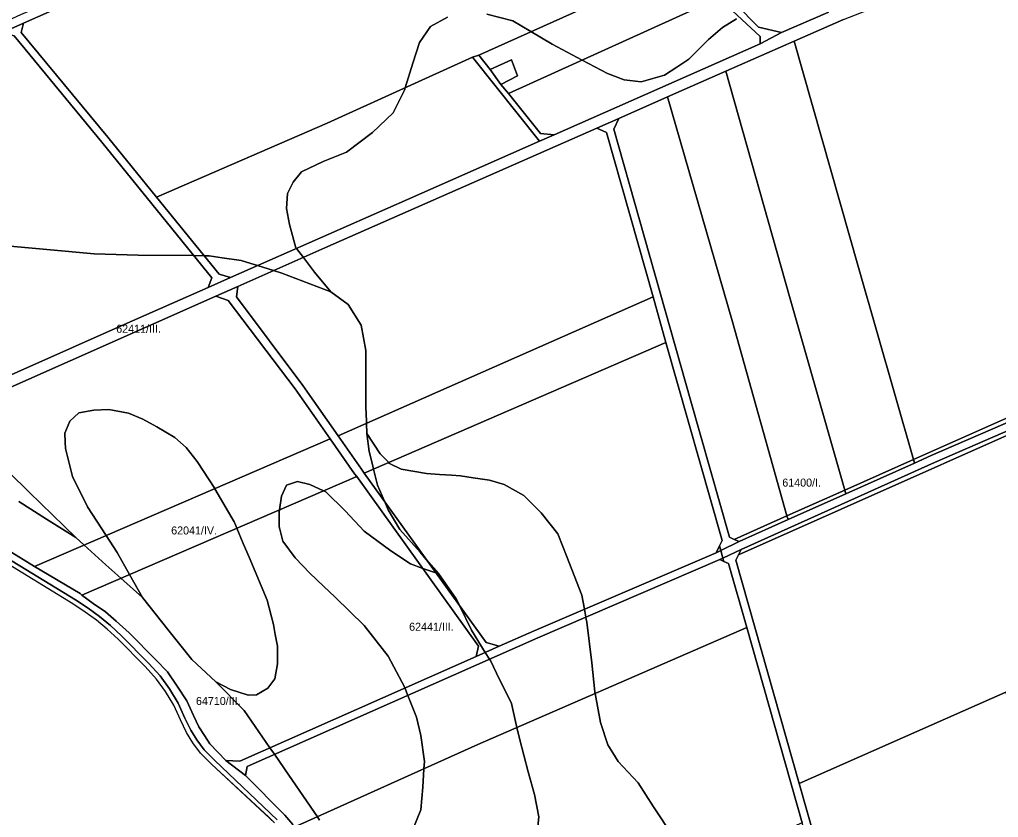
# Model space of a CAD drawing. Extents: x -522079 to -518833, y -1142400 to -1139961.
# Drawn here: x -521597 to -520985, y -1141508 to -1141010 of the extents above; entities that cross this region are included whole.
import ezdxf

# ---------------------------------------------------------------- set-up
doc = ezdxf.new("R2010")
doc.units = 0
for name, color, linetype in [('95560013', 7, 'Continuous'), ('95620013', 7, 'Continuous'), ('95630013', 7, 'Continuous'), ('95640013', 7, 'Continuous'), ('95660013', 7, 'Continuous')]:
    doc.layers.add(name, color=color, linetype=linetype)

msp = doc.modelspace()

# ---------------------------------------------------------------- linework, layer by layer
at = {"layer": '95560013'}
for points in [[(-521288.46, -1140863.02), (-521283.24, -1140866.3), (-521272.67, -1140872.95), (-521285.04, -1140873.12), (-521453.3, -1140949.4), (-521594.31, -1141011.83), (-521607.81, -1141017.81), (-521735.67, -1141074.42), (-521844.44, -1141121.41), (-521845.59, -1141127.96), (-521855.85, -1141115.33), (-521847.83, -1141117.27), (-521813.35, -1141102.46), (-521737.51, -1141069.87), (-521612.22, -1141013.76), (-521597.65, -1141007.23), (-521455.15, -1140944.86), (-521289.17, -1140869.28)], [(-521453.3, -1140949.4), (-521285.04, -1140873.12), (-521272.67, -1140872.95), (-521180.73, -1140973.62), (-521309.93, -1141031.69), (-521313.87, -1141033.11), (-521404.59, -1141074.2), (-521511.15, -1141120.5), (-521541.57, -1141083.01), (-521595.68, -1141017.57), (-521594.31, -1141011.83)], [(-520895.4, -1141219.71), (-520895.96, -1141221.04), (-521038.45, -1141284.46), (-521072.62, -1141164.33), (-521112.83, -1141022.98), (-521082.18, -1141009.47), (-521026.59, -1140987.63), (-520970.5, -1140967.09), (-520964.29, -1140970.32), (-520927.66, -1141102.94)], [(-521296.08, -1141050.04), (-521285.67, -1141044.64), (-521289.36, -1141034.73), (-521302.83, -1141040.76), (-521309.93, -1141031.69), (-521180.73, -1140973.62), (-521160.03, -1140995.91), (-521291.39, -1141055.81)], [(-521134.18, -1141024.63), (-521223.67, -1141064.26), (-521262.72, -1141081.47), (-521271.3, -1141080.74), (-521291.39, -1141055.81), (-521160.03, -1140995.91), (-521134.23, -1141020.21)], [(-521464.85, -1141170.68), (-521478.81, -1141176.87), (-521476.67, -1141170.91), (-521545.26, -1141086.06), (-521600.08, -1141019.71), (-521607.81, -1141017.81), (-521594.31, -1141011.83), (-521595.68, -1141017.57), (-521541.57, -1141083.01), (-521511.15, -1141120.5), (-521472.07, -1141168.66)], [(-521705, -1141272.16), (-521746.52, -1141232.38), (-521780.54, -1141201.02), (-521789.46, -1141193.57), (-521801.69, -1141180.84), (-521813.1, -1141167.95), (-521845.59, -1141127.96), (-521844.44, -1141121.41), (-521735.67, -1141074.42), (-521607.81, -1141017.81), (-521600.08, -1141019.71), (-521545.26, -1141086.06), (-521476.67, -1141170.91), (-521478.81, -1141176.87), (-521531.28, -1141200.09), (-521696.71, -1141273.51)], [(-521112.83, -1141022.98), (-521072.62, -1141164.33), (-521038.45, -1141284.46), (-521081.35, -1141303.56), (-521115.71, -1141182.49), (-521155.63, -1141041.85)], [(-521354.37, -1141121.84), (-521464.85, -1141170.68), (-521472.07, -1141168.66), (-521511.15, -1141120.5), (-521404.59, -1141074.2), (-521313.87, -1141033.11), (-521271.86, -1141085.49)], [(-521313.87, -1141033.11), (-521309.93, -1141031.69), (-521302.83, -1141040.76), (-521296.08, -1141050.04), (-521291.39, -1141055.81), (-521271.3, -1141080.74), (-521262.72, -1141081.47), (-521271.86, -1141085.49)], [(-521155.63, -1141041.85), (-521115.71, -1141182.49), (-521081.35, -1141303.56), (-521117.38, -1141319.6), (-521151.45, -1141198.34), (-521191.96, -1141057.88)], [(-521177.35, -1141247.92), (-521225.53, -1141078.04), (-521222.3, -1141071.25), (-521191.96, -1141057.88), (-521151.45, -1141198.34), (-521117.38, -1141319.6), (-521150.33, -1141334.27), (-521153.24, -1141332.9)], [(-521419.75, -1141238.15), (-521461.21, -1141182.74), (-521460.33, -1141176.23), (-521405.94, -1141152.24), (-521236.08, -1141077.32), (-521230.09, -1141080.11), (-521201.01, -1141182.77), (-521328.3, -1141238.94), (-521397.78, -1141269.61)], [(-521474.13, -1141182.35), (-521460.33, -1141176.23), (-521461.21, -1141182.74), (-521419.75, -1141238.15), (-521397.78, -1141269.61), (-521383.22, -1141290.47), (-521381.4, -1141292.99), (-521305.3, -1141398.78), (-521297.15, -1141401.04), (-521311.57, -1141407.43), (-521310.04, -1141400.96), (-521386.12, -1141295.04), (-521387.39, -1141293.27), (-521402.72, -1141271.39), (-521424.55, -1141240.21), (-521466.3, -1141184.96)], [(-521587.36, -1141351.16), (-521604.24, -1141340.75), (-521628.15, -1141324.02), (-521671.77, -1141299.69), (-521692.02, -1141284.07), (-521691.15, -1141278.7), (-521609.81, -1141242.59), (-521474.13, -1141182.35), (-521466.3, -1141184.96), (-521424.55, -1141240.21), (-521402.72, -1141271.39)], [(-521192.96, -1141211.21), (-521381.4, -1141292.99), (-521383.22, -1141290.47), (-521397.78, -1141269.61), (-521328.3, -1141238.94), (-521201.01, -1141182.77)], [(-521157.91, -1141334.94), (-521159.51, -1141338.32), (-521161.56, -1141342.65), (-521275.3, -1141391.36), (-521297.15, -1141401.04), (-521305.3, -1141398.78), (-521381.4, -1141292.99), (-521192.96, -1141211.21)], [(-520851.22, -1141372.34), (-520980.65, -1141429.68), (-521109.72, -1141486.85), (-521149.23, -1141347.36), (-521147.68, -1141344.03), (-520893.13, -1141230.74), (-520889.86, -1141232.13)], [(-521387.39, -1141293.27), (-521386.12, -1141295.04), (-521557.71, -1141369.1), (-521558.92, -1141368.2), (-521587.36, -1141351.16), (-521402.72, -1141271.39)], [(-521386.12, -1141295.04), (-521310.04, -1141400.96), (-521311.57, -1141407.43), (-521459, -1141472.78), (-521467.85, -1141472.41), (-521477.75, -1141461.99), (-521481.18, -1141456.84), (-521484.69, -1141451.44), (-521488.03, -1141444.36), (-521492.17, -1141435.06), (-521498.23, -1141425.96), (-521504.19, -1141417.07), (-521511.47, -1141409.59), (-521528.31, -1141392.77), (-521536.29, -1141385.49), (-521543.06, -1141379.52), (-521550.74, -1141374.27), (-521557.71, -1141369.1)], [(-521161.56, -1141342.65), (-521159.51, -1141338.32), (-521158.68, -1141341.24)], [(-521467.85, -1141472.41), (-521459, -1141472.78), (-521311.57, -1141407.43), (-521297.15, -1141401.04), (-521275.3, -1141391.36), (-521161.56, -1141342.65), (-521158.68, -1141341.24), (-521157.35, -1141345.97), (-521159.26, -1141346.88), (-521272.96, -1141395.84), (-521454.54, -1141476.12), (-521455.62, -1141481.81)], [(-521431.09, -1141506.63), (-521455.62, -1141481.81), (-521454.54, -1141476.12), (-521272.96, -1141395.84), (-521159.26, -1141346.88), (-521156.76, -1141348.04), (-521153.82, -1141349.39), (-521142.48, -1141389.44), (-521310.56, -1141462.49), (-521425.07, -1141514.17), (-521426.04, -1141512.48)], [(-521156.76, -1141348.04), (-521159.26, -1141346.88), (-521157.35, -1141345.97)], [(-521378.39, -1141629.5), (-521389.3, -1141621.72), (-521393.54, -1141617.98), (-521399.61, -1141612.42), (-521404.05, -1141606.86), (-521406.05, -1141602.85), (-521409.49, -1141593.05), (-521412.01, -1141585.06), (-521414.13, -1141574.69), (-521415.34, -1141566.3), (-521417.47, -1141538.2), (-521418.07, -1141529.55), (-521421, -1141521.26), (-521425.07, -1141514.17), (-521310.56, -1141462.49), (-521142.48, -1141389.44), (-521107.96, -1141511.35), (-521234.07, -1141566.44)], [(-520980.65, -1141429.68), (-520955.18, -1141519.6), (-521084.21, -1141576.91), (-521109.72, -1141486.85)]]:
    msp.add_lwpolyline(points, close=True, dxfattribs=at)
at = {"layer": '95620013'}
msp.add_lwpolyline([(-521283.37, -1140860.94), (-521307.86, -1140833.61), (-521298.55, -1140826.47), (-521220.23, -1140832.37), (-521184.18, -1140870.5), (-521185.72, -1140871.68), (-521143.12, -1140927.46), (-521088.9, -1141000.66), (-521091.97, -1141005.03), (-521120.79, -1141017.67), (-521135.25, -1141014.2), (-521191.17, -1140957.11), (-521275.9, -1140861.47), (-521279.53, -1140861.89)], close=True, dxfattribs=at)
at = {"layer": '95630013'}
for points in [[(-521437.41, -1141511.31), (-521476.9, -1141474.65), (-521483.59, -1141467.79), (-521488.42, -1141461.33), (-521492.43, -1141454.93), (-521496.24, -1141447.12), (-521500.39, -1141437.89), (-521505.54, -1141429.29), (-521511.22, -1141421.52), (-521518.22, -1141413.8), (-521535.13, -1141396.73), (-521541.97, -1141390.39), (-521548.66, -1141384.81), (-521555.61, -1141379.71), (-521563.41, -1141374.64), (-521610.54, -1141345.88)], [(-521608.95, -1141343.32), (-521561.83, -1141372.1), (-521553.85, -1141377.26), (-521546.79, -1141382.47), (-521539.97, -1141388.19), (-521532.97, -1141394.62), (-521516.02, -1141411.74), (-521508.94, -1141419.63), (-521503.06, -1141427.66), (-521497.72, -1141436.55), (-521493.43, -1141445.97), (-521489.81, -1141453.49), (-521485.96, -1141459.56), (-521481.44, -1141465.72), (-521474.82, -1141472.48), (-521435.7, -1141509.5)]]:
    msp.add_lwpolyline(points, dxfattribs=at)
at = {"layer": '95640013'}
for points in [[(-521134.18, -1141024.63), (-521134.23, -1141020.21), (-521160.03, -1140995.91), (-521180.73, -1140973.62), (-521272.67, -1140872.95), (-521283.24, -1140866.3), (-521275.9, -1140861.47), (-521191.17, -1140957.11), (-521135.25, -1141014.2), (-521120.79, -1141017.67)], [(-521285.67, -1141044.64), (-521296.08, -1141050.04), (-521302.83, -1141040.76), (-521289.36, -1141034.73)], [(-521222.3, -1141071.25), (-521225.53, -1141078.04), (-521177.35, -1141247.92), (-521153.24, -1141332.9), (-521150.33, -1141334.27), (-521147.33, -1141335.67), (-521158.68, -1141341.24), (-521159.51, -1141338.32), (-521157.91, -1141334.94), (-521192.96, -1141211.21), (-521201.01, -1141182.77), (-521230.09, -1141080.11), (-521236.08, -1141077.32)], [(-520895.96, -1141221.04), (-520897.83, -1141225.78), (-521027.41, -1141281.92), (-521037.84, -1141286.59), (-521038.45, -1141284.46)], [(-520893.13, -1141230.74), (-521147.68, -1141344.03), (-521146.08, -1141340.6), (-521025.25, -1141286.2), (-520895.38, -1141229.74)], [(-521037.84, -1141286.59), (-521080.71, -1141305.81), (-521081.35, -1141303.56), (-521038.45, -1141284.46)], [(-521081.35, -1141303.56), (-521080.71, -1141305.81), (-521116.71, -1141321.95), (-521117.38, -1141319.6)], [(-521147.33, -1141335.67), (-521150.33, -1141334.27), (-521117.38, -1141319.6), (-521116.71, -1141321.95)], [(-521147.68, -1141344.03), (-521149.23, -1141347.36), (-521109.72, -1141486.85), (-521084.21, -1141576.91), (-521078.78, -1141596.05), (-521077.42, -1141600.82), (-521086.66, -1141604.9), (-521083.41, -1141598.05), (-521107.96, -1141511.35), (-521142.48, -1141389.44), (-521153.82, -1141349.39), (-521156.76, -1141348.04), (-521157.35, -1141345.97), (-521146.08, -1141340.6)]]:
    msp.add_lwpolyline(points, close=True, dxfattribs=at)
for points in [[(-521082.18, -1141009.47), (-521112.83, -1141022.98), (-521155.63, -1141041.85), (-521191.96, -1141057.88), (-521222.3, -1141071.25), (-521236.08, -1141077.32), (-521405.94, -1141152.24), (-521460.33, -1141176.23), (-521474.13, -1141182.35), (-521609.81, -1141242.59), (-521691.15, -1141278.7), (-521692.02, -1141284.07), (-521705, -1141272.16), (-521696.71, -1141273.51), (-521531.28, -1141200.09), (-521478.81, -1141176.87), (-521464.85, -1141170.68), (-521354.37, -1141121.84), (-521271.86, -1141085.49), (-521262.72, -1141081.47), (-521223.67, -1141064.26), (-521134.18, -1141024.63), (-521120.79, -1141017.67), (-521091.97, -1141005.03)], [(-520895.38, -1141229.74), (-521025.25, -1141286.2), (-521146.08, -1141340.6), (-521157.35, -1141345.97), (-521158.68, -1141341.24), (-521147.33, -1141335.67), (-521116.71, -1141321.95), (-521080.71, -1141305.81), (-521037.84, -1141286.59), (-521027.41, -1141281.92), (-520897.83, -1141225.78)], [(-521604.24, -1141340.75), (-521587.36, -1141351.16), (-521558.92, -1141368.2), (-521557.71, -1141369.1), (-521550.74, -1141374.27), (-521543.06, -1141379.52), (-521536.29, -1141385.49), (-521528.31, -1141392.77), (-521511.47, -1141409.59), (-521504.19, -1141417.07), (-521498.23, -1141425.96), (-521492.17, -1141435.06), (-521488.03, -1141444.36), (-521484.69, -1141451.44), (-521481.18, -1141456.84), (-521477.75, -1141461.99), (-521467.85, -1141472.41), (-521455.62, -1141481.81), (-521431.09, -1141506.63), (-521426.04, -1141512.48)], [(-521435.7, -1141509.5), (-521474.82, -1141472.48), (-521481.44, -1141465.72), (-521485.96, -1141459.56), (-521489.81, -1141453.49), (-521493.43, -1141445.97), (-521497.72, -1141436.55), (-521503.06, -1141427.66), (-521508.94, -1141419.63), (-521516.02, -1141411.74), (-521532.97, -1141394.62), (-521539.97, -1141388.19), (-521546.79, -1141382.47), (-521553.85, -1141377.26), (-521561.83, -1141372.1), (-521608.95, -1141343.32)]]:
    msp.add_lwpolyline(points, dxfattribs=at)
at = {"layer": '95660013'}
for points in [[(-521329.43, -1141007.98), (-521339.94, -1141013.83), (-521346.95, -1141023.8), (-521351.04, -1141036.69), (-521355.81, -1141052.1), (-521356.3, -1141053.68), (-521363.31, -1141067.75), (-521376.16, -1141080.05), (-521392.52, -1141092.36), (-521407.12, -1141098.22), (-521420.56, -1141104.67), (-521425.81, -1141111.11), (-521426.69, -1141112.87), (-521429.32, -1141118.14), (-521429.9, -1141127.52), (-521428.15, -1141137.48), (-521424.06, -1141152.13), (-521423.76, -1141152.52), (-521419.42, -1141158.18), (-521412.38, -1141167.36), (-521402.29, -1141179.6), (-521432.87, -1141168.01), (-521438.03, -1141166.39), (-521448.04, -1141163.25), (-521452.23, -1141161.94), (-521458.24, -1141160.06), (-521470.15, -1141158.29), (-521478.17, -1141157.1), (-521479.52, -1141157.09), (-521481.47, -1141157.07), (-521487.91, -1141157), (-521522.57, -1141156.65), (-521549.98, -1141155.96), (-521579.71, -1141153.25), (-521604.79, -1141150.97)], [(-521188.48, -1141519.97), (-521200.71, -1141501.34), (-521210.22, -1141486.34), (-521222.9, -1141473.16), (-521226.22, -1141467.7), (-521229.25, -1141462.71), (-521233.78, -1141448.62), (-521237.2, -1141430.6), (-521237.4, -1141429.53), (-521239.21, -1141411.36), (-521242.38, -1141385.91), (-521242.72, -1141384.12), (-521242.95, -1141382.92), (-521243.89, -1141377.91), (-521245.55, -1141369.09), (-521251.72, -1141353.18), (-521255.07, -1141344.56), (-521257.4, -1141338.72), (-521260.5, -1141330.92), (-521270.92, -1141317.75), (-521281.8, -1141306.84), (-521294.03, -1141300.02), (-521303.09, -1141297.29), (-521313.39, -1141295.74), (-521321.21, -1141294.57), (-521327.01, -1141294.2), (-521334.39, -1141293.72), (-521342.5, -1141293.2), (-521358.35, -1141290.48), (-521365.6, -1141286.84), (-521366.09, -1141286.35), (-521371.49, -1141280.93), (-521379.87, -1141268.21), (-521380.05, -1141261.78), (-521380.06, -1141261.15), (-521380.08, -1141260.38), (-521380.32, -1141251.62), (-521380.32, -1141230.49), (-521380.32, -1141216.18), (-521383.27, -1141200.5), (-521391.42, -1141187.55), (-521402.29, -1141179.6), (-521412.38, -1141167.36), (-521419.42, -1141158.18), (-521423.76, -1141152.52), (-521424.06, -1141152.13), (-521428.15, -1141137.48), (-521429.9, -1141127.52), (-521429.32, -1141118.14), (-521426.69, -1141112.87), (-521425.81, -1141111.11), (-521420.56, -1141104.67), (-521407.12, -1141098.22), (-521392.52, -1141092.36), (-521376.16, -1141080.05), (-521363.31, -1141067.75), (-521356.3, -1141053.68), (-521355.81, -1141052.1), (-521351.04, -1141036.69), (-521346.95, -1141023.8), (-521339.94, -1141013.83), (-521329.43, -1141007.98)], [(-521304.89, -1141006.22), (-521288.54, -1141010.32), (-521277.31, -1141017.02), (-521264, -1141024.97), (-521245.33, -1141034.81), (-521229.54, -1141043.13), (-521219.02, -1141047.24), (-521208.51, -1141048.41), (-521193.9, -1141044.31), (-521186.08, -1141039.18), (-521178.72, -1141034.34), (-521177.36, -1141032.99), (-521166.45, -1141022.04), (-521157.69, -1141014.42), (-521148.92, -1141009.15)], [(-521148.92, -1141009.15), (-521157.69, -1141014.42), (-521166.45, -1141022.04), (-521177.36, -1141032.99), (-521178.72, -1141034.34), (-521186.08, -1141039.18), (-521193.9, -1141044.31), (-521208.51, -1141048.41), (-521219.02, -1141047.24), (-521229.54, -1141043.13), (-521245.33, -1141034.81), (-521264, -1141024.97), (-521277.31, -1141017.02), (-521288.54, -1141010.32), (-521304.89, -1141006.22)], [(-521604.79, -1141150.97), (-521579.71, -1141153.25), (-521549.98, -1141155.96), (-521522.57, -1141156.65), (-521487.91, -1141157), (-521481.47, -1141157.07), (-521479.52, -1141157.09), (-521478.17, -1141157.1), (-521470.15, -1141158.29), (-521458.24, -1141160.06), (-521452.23, -1141161.94), (-521448.04, -1141163.25), (-521438.03, -1141166.39), (-521432.87, -1141168.01), (-521402.29, -1141179.6), (-521391.42, -1141187.55), (-521383.27, -1141200.5), (-521380.32, -1141216.18), (-521380.32, -1141230.49), (-521380.32, -1141251.62), (-521380.08, -1141260.38), (-521380.06, -1141261.15), (-521380.05, -1141261.78), (-521379.87, -1141268.21), (-521378.28, -1141279.34), (-521376.46, -1141286.74), (-521375.55, -1141290.45), (-521373.08, -1141300.48), (-521368.83, -1141310.46), (-521366.51, -1141315.93), (-521359.26, -1141328.2), (-521346.57, -1141342.28), (-521342.67, -1141346.82), (-521335.08, -1141355.66), (-521336.68, -1141355.16), (-521342.95, -1141353.19), (-521344.88, -1141352.45), (-521352.46, -1141349.55), (-521364.7, -1141341.37), (-521381.46, -1141329.1), (-521393.24, -1141316.38), (-521405.47, -1141304.57), (-521406.27, -1141304.2), (-521406.79, -1141303.96), (-521415.43, -1141300.02), (-521423.13, -1141298.2), (-521429.93, -1141300.48), (-521433.1, -1141307.29), (-521434.26, -1141315.82), (-521434.46, -1141317.29), (-521434.46, -1141326.38), (-521434.1, -1141327.81), (-521432.19, -1141335.47), (-521424.49, -1141345.92), (-521415.43, -1141355.46), (-521406.81, -1141363.62), (-521399.58, -1141370.46), (-521381.46, -1141388.18), (-521366.51, -1141407.27), (-521356.09, -1141426.81), (-521355.97, -1141427.11), (-521354.17, -1141431.74), (-521348.84, -1141445.44), (-521346.12, -1141456.8), (-521343.86, -1141473.16), (-521344.11, -1141477.63), (-521344.76, -1141489.07), (-521346.12, -1141503.16), (-521350.65, -1141514.51)], [(-521409.25, -1141509.65), (-521410.62, -1141507.65), (-521428.44, -1141481.62), (-521437.49, -1141468.58), (-521440.32, -1141464.5), (-521456.46, -1141441.25), (-521474, -1141423.33), (-521465, -1141428.01), (-521454, -1141431.68), (-521448.67, -1141431.35), (-521441.67, -1141427.34), (-521437.34, -1141421.32), (-521435.67, -1141411.96), (-521435.67, -1141400.93), (-521436.94, -1141393.68), (-521438.01, -1141387.56), (-521442.01, -1141372.18), (-521453.34, -1141345.44), (-521456.99, -1141336.81), (-521460.98, -1141327.35), (-521462.31, -1141324.22), (-521462.67, -1141323.37), (-521474.66, -1141302.65), (-521474.75, -1141302.51), (-521485.66, -1141285.6), (-521492.66, -1141276.91), (-521499.66, -1141270.55), (-521510.99, -1141263.87), (-521519.65, -1141259.19), (-521528.65, -1141255.51), (-521540.98, -1141253.17), (-521550.31, -1141253.51), (-521559.64, -1141255.18), (-521565.31, -1141260.52), (-521568.31, -1141267.88), (-521568.11, -1141273.46), (-521567.97, -1141277.58), (-521563.64, -1141294.96), (-521554.31, -1141314.01), (-521542.61, -1141331.83), (-521535.65, -1141342.43), (-521527.94, -1141356.25), (-521519.98, -1141370.51), (-521533.36, -1141358.59), (-521542.73, -1141350.24), (-521556.45, -1141337.8), (-521561.53, -1141333.19), (-521590.75, -1141304.79), (-521615.66, -1141280.48)], [(-521274.09, -1141523.6), (-521272.28, -1141507.7), (-521275, -1141493.61), (-521279.08, -1141479.52), (-521284.51, -1141458.62), (-521286.06, -1141451.84), (-521289.5, -1141436.81), (-521298.8, -1141417.81), (-521302.63, -1141410), (-521303.14, -1141409.18), (-521305.8, -1141404.87), (-521314.41, -1141390.91), (-521321.64, -1141376.07), (-521322.95, -1141373.36), (-521323.92, -1141371.37), (-521335.08, -1141355.66), (-521342.67, -1141346.82), (-521346.57, -1141342.28), (-521359.26, -1141328.2), (-521366.51, -1141315.93), (-521368.83, -1141310.46), (-521373.08, -1141300.48), (-521375.55, -1141290.45), (-521376.46, -1141286.74), (-521378.28, -1141279.34), (-521379.87, -1141268.21), (-521371.49, -1141280.93), (-521366.09, -1141286.35), (-521365.6, -1141286.84), (-521358.35, -1141290.48), (-521342.5, -1141293.2), (-521334.39, -1141293.72), (-521327.01, -1141294.2), (-521321.21, -1141294.57), (-521313.39, -1141295.74), (-521303.09, -1141297.29), (-521294.03, -1141300.02), (-521281.8, -1141306.84), (-521270.92, -1141317.75), (-521260.5, -1141330.92), (-521257.4, -1141338.72), (-521255.07, -1141344.56), (-521251.72, -1141353.18), (-521245.55, -1141369.09), (-521243.89, -1141377.91), (-521242.95, -1141382.92), (-521242.72, -1141384.12), (-521242.38, -1141385.91), (-521239.21, -1141411.36), (-521237.4, -1141429.53), (-521237.2, -1141430.6), (-521233.78, -1141448.62), (-521229.25, -1141462.71), (-521226.22, -1141467.7), (-521222.9, -1141473.16), (-521210.22, -1141486.34), (-521200.71, -1141501.34), (-521188.48, -1141519.97)], [(-521615.66, -1141280.48), (-521590.75, -1141304.79), (-521561.53, -1141333.19), (-521579.88, -1141321.61), (-521597.19, -1141310.6)], [(-521350.65, -1141514.51), (-521346.12, -1141503.16), (-521344.76, -1141489.07), (-521344.11, -1141477.63), (-521343.86, -1141473.16), (-521346.12, -1141456.8), (-521348.84, -1141445.44), (-521354.17, -1141431.74), (-521355.97, -1141427.11), (-521356.09, -1141426.81), (-521366.51, -1141407.27), (-521381.46, -1141388.18), (-521399.58, -1141370.46), (-521406.81, -1141363.62), (-521415.43, -1141355.46), (-521424.49, -1141345.92), (-521432.19, -1141335.47), (-521434.1, -1141327.81), (-521434.46, -1141326.38), (-521434.46, -1141317.29), (-521434.26, -1141315.82), (-521433.1, -1141307.29), (-521429.93, -1141300.48), (-521423.13, -1141298.2), (-521415.43, -1141300.02), (-521406.79, -1141303.96), (-521406.27, -1141304.2), (-521405.47, -1141304.57), (-521393.24, -1141316.38), (-521381.46, -1141329.1), (-521364.7, -1141341.37), (-521352.46, -1141349.55), (-521344.88, -1141352.45), (-521342.95, -1141353.19), (-521336.68, -1141355.16), (-521335.08, -1141355.66), (-521323.92, -1141371.37), (-521322.95, -1141373.36), (-521321.64, -1141376.07), (-521314.41, -1141390.91), (-521305.8, -1141404.87), (-521303.14, -1141409.18), (-521302.63, -1141410), (-521298.8, -1141417.81), (-521289.5, -1141436.81), (-521286.06, -1141451.84), (-521284.51, -1141458.62), (-521279.08, -1141479.52), (-521275, -1141493.61), (-521272.28, -1141507.7), (-521274.09, -1141523.6)], [(-521597.19, -1141310.6), (-521579.88, -1141321.61), (-521561.53, -1141333.19), (-521556.45, -1141337.8), (-521542.73, -1141350.24), (-521533.36, -1141358.59), (-521519.98, -1141370.51), (-521503.32, -1141391.57), (-521488.99, -1141409.29), (-521474, -1141423.33), (-521456.46, -1141441.25), (-521440.32, -1141464.5), (-521437.49, -1141468.58), (-521428.44, -1141481.62), (-521410.62, -1141507.65), (-521409.25, -1141509.65)], [(-521437.41, -1141511.31), (-521441.06, -1141507.92), (-521476.9, -1141474.65), (-521483.59, -1141467.79), (-521488.42, -1141461.33), (-521492.43, -1141454.93), (-521496.24, -1141447.12), (-521500.39, -1141437.89), (-521505.54, -1141429.29), (-521511.22, -1141421.52), (-521518.22, -1141413.8), (-521535.13, -1141396.73), (-521541.97, -1141390.39), (-521548.66, -1141384.81), (-521555.61, -1141379.71), (-521563.41, -1141374.64), (-521610.54, -1141345.88)]]:
    msp.add_lwpolyline(points, dxfattribs=at)
msp.add_lwpolyline([(-521448.67, -1141431.35), (-521454, -1141431.68), (-521465, -1141428.01), (-521474, -1141423.33), (-521488.99, -1141409.29), (-521503.32, -1141391.57), (-521519.98, -1141370.51), (-521527.94, -1141356.25), (-521535.65, -1141342.43), (-521542.61, -1141331.83), (-521554.31, -1141314.01), (-521563.64, -1141294.96), (-521567.97, -1141277.58), (-521568.11, -1141273.46), (-521568.31, -1141267.88), (-521565.31, -1141260.52), (-521559.64, -1141255.18), (-521550.31, -1141253.51), (-521540.98, -1141253.17), (-521528.65, -1141255.51), (-521519.65, -1141259.19), (-521510.99, -1141263.87), (-521499.66, -1141270.55), (-521492.66, -1141276.91), (-521485.66, -1141285.6), (-521474.75, -1141302.51), (-521474.66, -1141302.65), (-521462.67, -1141323.37), (-521462.31, -1141324.22), (-521460.98, -1141327.35), (-521456.99, -1141336.81), (-521453.34, -1141345.44), (-521442.01, -1141372.18), (-521438.01, -1141387.56), (-521436.94, -1141393.68), (-521435.67, -1141400.93), (-521435.67, -1141411.96), (-521437.34, -1141421.32), (-521441.67, -1141427.34)], close=True, dxfattribs=at)

# ---------------------------------------------------------------- texts
for s, rotation, p in [('62411/III.', 0, (-521536.3, -1141205.18)), ('61400/I.', 360, (-521120.3, -1141301.32)), ('62041/IV.', 0, (-521501.99, -1141331.2)), ('62441/III.', 0, (-521353.37, -1141391.37)), ('64710/III.', 360, (-521486.5, -1141437.75))]:
    msp.add_text(s, height=5, rotation=rotation, dxfattribs=at).set_placement(p)

doc.saveas('drawing.dxf')
